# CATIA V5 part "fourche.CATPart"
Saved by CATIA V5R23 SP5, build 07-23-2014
Part number: fourche
Definition: fourche
Source: made
Bounding box of the stored display mesh (mm): x -75 to 36, y -17 to 17, z -27.5 to 27.5
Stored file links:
  C:\wamp\www\COURS\CONCEPTION GMP1\TITRE 01-CATIA VOLUMIQUE\05--ACTIONNEUR DE VANNE\prof\CORRECTION\Assemblage\fourche.CATPart
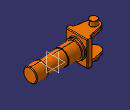
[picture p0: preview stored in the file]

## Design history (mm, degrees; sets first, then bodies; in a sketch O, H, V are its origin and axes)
Set1
  Plane1: type Offset, RefPlane face of Solid1, Offset 1.5, reversed
Body1 "NONE" (main body)
  Solid1 "Manifold Solid #132": solid without history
